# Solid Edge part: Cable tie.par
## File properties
Author: conerly
Template: Normal.par
Last saved by: alogan
Revision: 36
Application: Solid Edge
Density: 1024.000 kg/m^3
Accuracy: 0.990
Material: ABS Plastic, high impact
Face Style: Red
Fill Style: ANSI34(Plastic)
Virtual Style: Red (Shiny)
Coef. of Thermal Exp: 9e-05
Thermal Conductivity: 0.2
Specific Heat: 0.0
Modulus of Elasticity: 1378951400.0
Poisson's Ratio: 0.4
Yield Stress: 31026406.5
Ultimate Stress: 0.0
Elongation: 0.0
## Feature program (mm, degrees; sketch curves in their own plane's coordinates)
sketch for "unnamed Protrusion 1" plane through (0, 0, 0) normal (0, 0, 1) x-axis (1, 0, 0)
  line (-41.7139, -4.7993) -> (-16.3139, -4.7993)
  line (-16.3139, -4.7993) -> (-16.3139, 20.6007)
  line (-16.3139, 20.6007) -> (-41.7139, 20.6007)
  line (-41.7139, 20.6007) -> (-41.7139, -4.7993)
  dimension (linear) = 41.7139
  dimension (linear) = 16.3139
extrude "unnamed Protrusion 1" add finite 3.175 along +normal
sketch for "ExtrudedProtrusion_4" #1 plane through (0, 7.9007, 0) normal (0, -1, 0) x-axis (1, 0, 0)
  circle centre (-29.0139, 22.9724) radius 12.7
sketch for "ExtrudedProtrusion_4" #2 plane through (0, 7.9007, 0) normal (0, -1, 0) x-axis (1, 0, 0)
  circle centre (-29.0139, 22.9724) radius 15.875
extrude "ExtrudedProtrusion_4" add finite 12.7 symmetric
sketch for "unnamed Protrusion 2" plane through (-34.2139, 13.1007, 3.175) normal (0, 0, 1) x-axis (0, 1, 0)
extrude "unnamed Protrusion 2" add through along +normal
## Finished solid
Body 1: solid body, 12 faces, 26 edges, 16 vertices.
  Faces by surface: plane 10, cylinder 2
  Edges by curve: line 22, circle 4
Bounding box of the edges (mm): 31.750 x 25.400 x 38.847, from (-44.8889, -4.7993, 0) to (-13.1389, 20.6007, 38.8474).
Cylindrical faces by radius (mm): R12.7 x1, R15.875 x1
Planar faces by outward normal: +x 2, +y 2, +z 1, -x 2, -y 2, -z 1
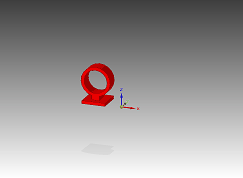
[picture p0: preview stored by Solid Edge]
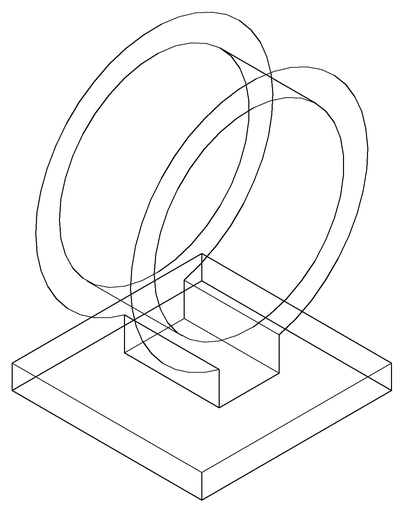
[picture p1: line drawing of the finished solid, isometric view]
